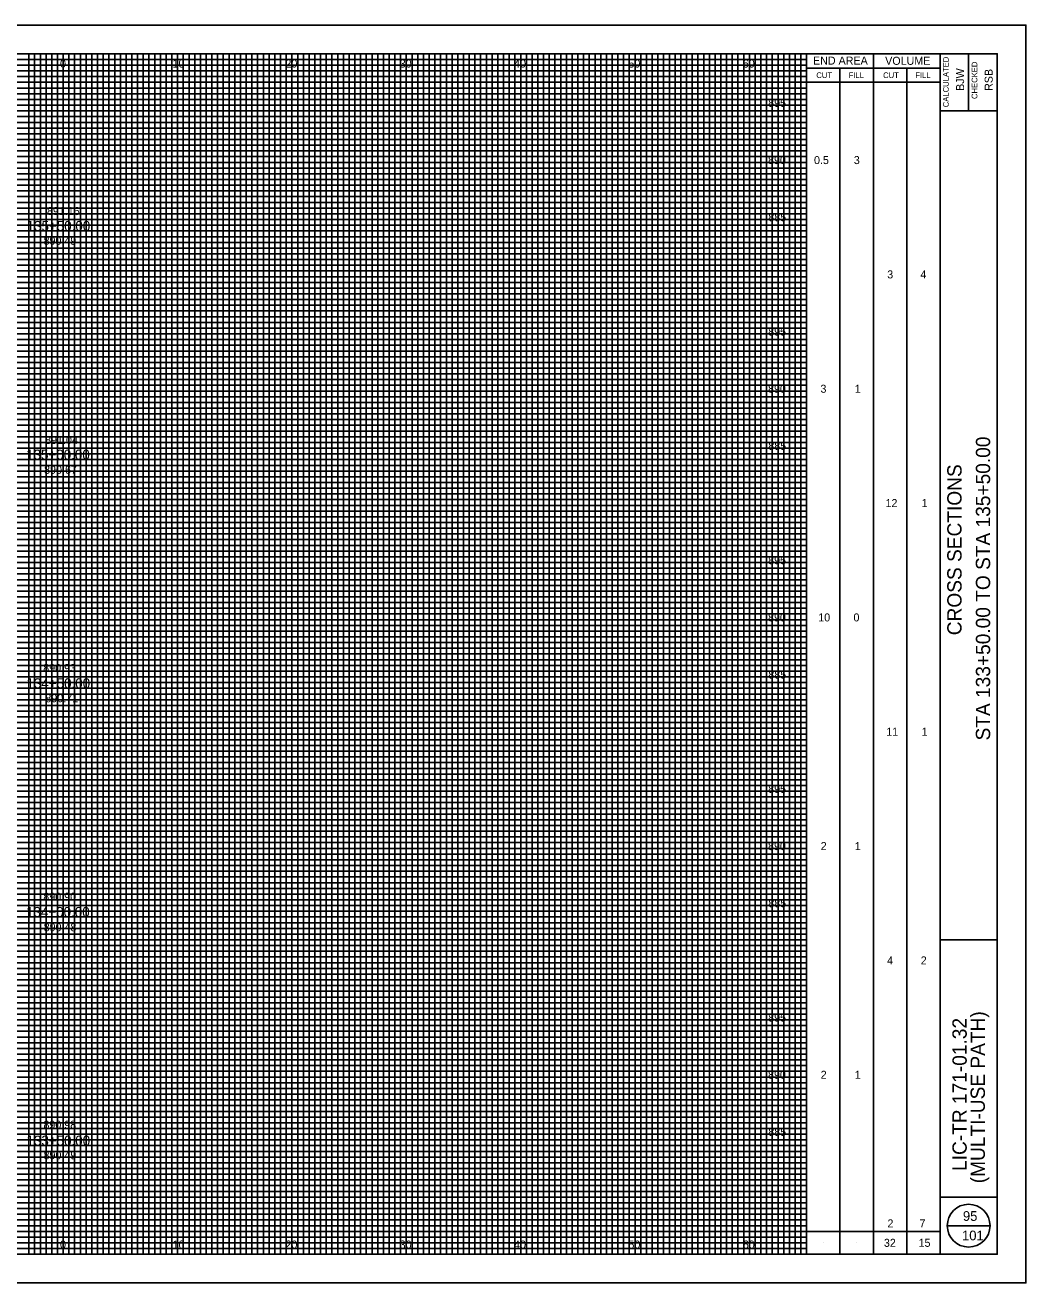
# Model space of a CAD drawing. Extents: x -10 to 160, y -2 to 3672.
# Drawn here: x 72.5 to 160, y 2987.5 to 3097.5 of the extents above; entities that cross this region are included whole.
import ezdxf

# ---------------------------------------------------------------- set-up
doc = ezdxf.new("R2010")
doc.units = 0
for name, color, linetype in [('SH_Border', 7, 'Continuous'), ('SH_Cut_Line', 7, 'Continuous'), ('SH_Data', 7, 'Continuous'), ('SH_Major_Grid_Line', 7, 'Continuous'), ('SH_Minor_Grid_Line', 7, 'Continuous'), ('SH_Text', 7, 'Continuous'), ('TX_P_10', 7, 'Continuous'), ('TX_X_10', 7, 'Continuous')]:
    doc.layers.add(name, color=color, linetype=linetype)

msp = doc.modelspace()

# ---------------------------------------------------------------- linework, layer by layer
at = {"layer": 'SH_Border'}
for p, q in [((152.5, 2990), (152.5, 3095)), ((155, 3095), (155, 3090)), ((152.5, 3090), (157.5, 3090)), ((152.5, 3017.5), (157.5, 3017.5)), ((152.5, 2995), (157.5, 2995))]:
    msp.add_line(p, q, dxfattribs=at)
msp.add_lwpolyline([(0, 3095), (157.5, 3095), (157.5, 2990), (0, 2990)], close=True, dxfattribs=at)
at = {"layer": 'SH_Cut_Line'}
msp.add_lwpolyline([(-10, 2987.5), (160, 2987.5), (160, 3097.5), (-10, 3097.5)], close=True, dxfattribs=at)
at = {"layer": 'SH_Data'}
for p, q in [((140.83, 2990), (140.83, 3095)), ((146.67, 2990), (146.67, 3095)), ((140.83, 3093.75), (152.5, 3093.75)), ((143.75, 2990), (143.75, 3093.75)), ((149.58, 2990), (149.58, 3093.75)), ((140.83, 3092.5), (152.5, 3092.5)), ((140.83, 2992), (152.5, 2992)), ((153.12, 2992.5), (156.88, 2992.5)), ((142.29, 2991), (142.29, 2991)), ((145.21, 2991), (145.21, 2991)), ((148.12, 2991), (148.12, 2991)), ((151.04, 2991), (151.04, 2991))]:
    msp.add_line(p, q, dxfattribs=at)
msp.add_circle((155, 2992.5), 1.87, dxfattribs=at)
at = {"layer": 'SH_Major_Grid_Line'}
for p, q in [((75.83, 2990), (75.83, 3095)), ((80.83, 2990), (80.83, 3095)), ((85.83, 2990), (85.83, 3095)), ((90.83, 2990), (90.83, 3095)), ((95.83, 2990), (95.83, 3095)), ((100.83, 2990), (100.83, 3095)), ((105.83, 2990), (105.83, 3095)), ((110.83, 2990), (110.83, 3095)), ((115.83, 2990), (115.83, 3095)), ((120.83, 2990), (120.83, 3095)), ((125.83, 2990), (125.83, 3095)), ((130.83, 2990), (130.83, 3095)), ((135.83, 2990), (135.83, 3095)), ((5.83, 3090), (140.83, 3090)), ((5.83, 3085), (140.83, 3085)), ((5.83, 3080), (140.83, 3080)), ((5.83, 3075), (140.83, 3075)), ((5.83, 3070), (140.83, 3070)), ((5.83, 3065), (140.83, 3065)), ((5.83, 3060), (140.83, 3060)), ((5.83, 3055), (140.83, 3055)), ((5.83, 3050), (140.83, 3050)), ((5.83, 3045), (140.83, 3045)), ((5.83, 3040), (140.83, 3040)), ((5.83, 3035), (140.83, 3035)), ((5.83, 3030), (140.83, 3030)), ((5.83, 3025), (140.83, 3025)), ((5.83, 3020), (140.83, 3020)), ((5.83, 3015), (140.83, 3015)), ((5.83, 3010), (140.83, 3010)), ((5.83, 3005), (140.83, 3005)), ((5.83, 3000), (140.83, 3000)), ((5.83, 2995), (140.83, 2995))]:
    msp.add_line(p, q, dxfattribs=at)
at = {"layer": 'SH_Minor_Grid_Line'}
for p, q in [((5.83, 3094.5), (140.83, 3094.5)), ((72.83, 2990), (72.83, 3095)), ((73.33, 2990), (73.33, 3095)), ((73.83, 2990), (73.83, 3095)), ((74.33, 2990), (74.33, 3095)), ((74.83, 2990), (74.83, 3095)), ((75.33, 2990), (75.33, 3095)), ((76.33, 2990), (76.33, 3095)), ((76.83, 2990), (76.83, 3095)), ((77.33, 2990), (77.33, 3095)), ((77.83, 2990), (77.83, 3095)), ((78.33, 2990), (78.33, 3095)), ((78.83, 2990), (78.83, 3095)), ((79.33, 2990), (79.33, 3095)), ((79.83, 2990), (79.83, 3095)), ((80.33, 2990), (80.33, 3095)), ((81.33, 2990), (81.33, 3095)), ((81.83, 2990), (81.83, 3095)), ((82.33, 2990), (82.33, 3095)), ((82.83, 2990), (82.83, 3095)), ((83.33, 2990), (83.33, 3095)), ((83.83, 2990), (83.83, 3095)), ((84.33, 2990), (84.33, 3095)), ((84.83, 2990), (84.83, 3095)), ((85.33, 2990), (85.33, 3095)), ((86.33, 2990), (86.33, 3095)), ((86.83, 2990), (86.83, 3095)), ((87.33, 2990), (87.33, 3095)), ((87.83, 2990), (87.83, 3095)), ((88.33, 2990), (88.33, 3095)), ((88.83, 2990), (88.83, 3095)), ((89.33, 2990), (89.33, 3095)), ((89.83, 2990), (89.83, 3095)), ((90.33, 2990), (90.33, 3095)), ((91.33, 2990), (91.33, 3095)), ((91.83, 2990), (91.83, 3095)), ((92.33, 2990), (92.33, 3095)), ((92.83, 2990), (92.83, 3095)), ((93.33, 2990), (93.33, 3095)), ((93.83, 2990), (93.83, 3095)), ((94.33, 2990), (94.33, 3095)), ((94.83, 2990), (94.83, 3095)), ((95.33, 2990), (95.33, 3095)), ((96.33, 2990), (96.33, 3095)), ((96.83, 2990), (96.83, 3095)), ((97.33, 2990), (97.33, 3095)), ((97.83, 2990), (97.83, 3095)), ((98.33, 2990), (98.33, 3095)), ((98.83, 2990), (98.83, 3095)), ((99.33, 2990), (99.33, 3095)), ((99.83, 2990), (99.83, 3095)), ((100.33, 2990), (100.33, 3095)), ((101.33, 2990), (101.33, 3095)), ((101.83, 2990), (101.83, 3095)), ((102.33, 2990), (102.33, 3095)), ((102.83, 2990), (102.83, 3095)), ((103.33, 2990), (103.33, 3095)), ((103.83, 2990), (103.83, 3095)), ((104.33, 2990), (104.33, 3095)), ((104.83, 2990), (104.83, 3095)), ((105.33, 2990), (105.33, 3095)), ((106.33, 2990), (106.33, 3095)), ((106.83, 2990), (106.83, 3095)), ((107.33, 2990), (107.33, 3095)), ((107.83, 2990), (107.83, 3095)), ((108.33, 2990), (108.33, 3095)), ((108.83, 2990), (108.83, 3095)), ((109.33, 2990), (109.33, 3095)), ((109.83, 2990), (109.83, 3095)), ((110.33, 2990), (110.33, 3095)), ((111.33, 2990), (111.33, 3095)), ((111.83, 2990), (111.83, 3095)), ((112.33, 2990), (112.33, 3095)), ((112.83, 2990), (112.83, 3095)), ((113.33, 2990), (113.33, 3095)), ((113.83, 2990), (113.83, 3095)), ((114.33, 2990), (114.33, 3095)), ((114.83, 2990), (114.83, 3095)), ((115.33, 2990), (115.33, 3095)), ((116.33, 2990), (116.33, 3095)), ((116.83, 2990), (116.83, 3095)), ((117.33, 2990), (117.33, 3095)), ((117.83, 2990), (117.83, 3095)), ((118.33, 2990), (118.33, 3095)), ((118.83, 2990), (118.83, 3095)), ((119.33, 2990), (119.33, 3095)), ((119.83, 2990), (119.83, 3095)), ((120.33, 2990), (120.33, 3095)), ((121.33, 2990), (121.33, 3095)), ((121.83, 2990), (121.83, 3095)), ((122.33, 2990), (122.33, 3095)), ((122.83, 2990), (122.83, 3095)), ((123.33, 2990), (123.33, 3095)), ((123.83, 2990), (123.83, 3095)), ((124.33, 2990), (124.33, 3095)), ((124.83, 2990), (124.83, 3095)), ((125.33, 2990), (125.33, 3095)), ((126.33, 2990), (126.33, 3095)), ((126.83, 2990), (126.83, 3095)), ((127.33, 2990), (127.33, 3095)), ((127.83, 2990), (127.83, 3095)), ((128.33, 2990), (128.33, 3095)), ((128.83, 2990), (128.83, 3095)), ((129.33, 2990), (129.33, 3095)), ((129.83, 2990), (129.83, 3095)), ((130.33, 2990), (130.33, 3095)), ((131.33, 2990), (131.33, 3095)), ((131.83, 2990), (131.83, 3095)), ((132.33, 2990), (132.33, 3095)), ((132.83, 2990), (132.83, 3095)), ((133.33, 2990), (133.33, 3095)), ((133.83, 2990), (133.83, 3095)), ((134.33, 2990), (134.33, 3095)), ((134.83, 2990), (134.83, 3095)), ((135.33, 2990), (135.33, 3095)), ((136.33, 2990), (136.33, 3095)), ((136.83, 2990), (136.83, 3095)), ((137.33, 2990), (137.33, 3095)), ((137.83, 2990), (137.83, 3095)), ((138.33, 2990), (138.33, 3095)), ((138.83, 2990), (138.83, 3095)), ((139.33, 2990), (139.33, 3095)), ((139.83, 2990), (139.83, 3095)), ((140.33, 2990), (140.33, 3095)), ((5.83, 3094), (140.83, 3094)), ((5.83, 3093.5), (140.83, 3093.5)), ((5.83, 3093), (140.83, 3093)), ((5.83, 3092.5), (140.83, 3092.5)), ((5.83, 3092), (140.83, 3092)), ((5.83, 3091.5), (140.83, 3091.5)), ((5.83, 3091), (140.83, 3091)), ((5.83, 3090.5), (140.83, 3090.5)), ((5.83, 3089.5), (140.83, 3089.5)), ((5.83, 3089), (140.83, 3089)), ((5.83, 3088.5), (140.83, 3088.5)), ((5.83, 3088), (140.83, 3088)), ((5.83, 3087.5), (140.83, 3087.5)), ((5.83, 3087), (140.83, 3087)), ((5.83, 3086.5), (140.83, 3086.5)), ((5.83, 3086), (140.83, 3086)), ((5.83, 3085.5), (140.83, 3085.5)), ((5.83, 3084.5), (140.83, 3084.5)), ((5.83, 3084), (140.83, 3084)), ((5.83, 3083.5), (140.83, 3083.5)), ((5.83, 3083), (140.83, 3083)), ((5.83, 3082.5), (140.83, 3082.5)), ((5.83, 3082), (140.83, 3082)), ((5.83, 3081.5), (140.83, 3081.5)), ((5.83, 3081), (140.83, 3081)), ((5.83, 3080.5), (140.83, 3080.5)), ((5.83, 3079.5), (140.83, 3079.5)), ((5.83, 3079), (140.83, 3079)), ((5.83, 3078.5), (140.83, 3078.5)), ((5.83, 3078), (140.83, 3078)), ((5.83, 3077.5), (140.83, 3077.5)), ((5.83, 3077), (140.83, 3077)), ((5.83, 3076.5), (140.83, 3076.5)), ((5.83, 3076), (140.83, 3076)), ((5.83, 3075.5), (140.83, 3075.5)), ((5.83, 3074.5), (140.83, 3074.5)), ((5.83, 3074), (140.83, 3074)), ((5.83, 3073.5), (140.83, 3073.5)), ((5.83, 3073), (140.83, 3073)), ((5.83, 3072.5), (140.83, 3072.5)), ((5.83, 3072), (140.83, 3072)), ((5.83, 3071.5), (140.83, 3071.5)), ((5.83, 3071), (140.83, 3071)), ((5.83, 3070.5), (140.83, 3070.5)), ((5.83, 3069.5), (140.83, 3069.5)), ((5.83, 3069), (140.83, 3069)), ((5.83, 3068.5), (140.83, 3068.5)), ((5.83, 3068), (140.83, 3068)), ((5.83, 3067.5), (140.83, 3067.5)), ((5.83, 3067), (140.83, 3067)), ((5.83, 3066.5), (140.83, 3066.5)), ((5.83, 3066), (140.83, 3066)), ((5.83, 3065.5), (140.83, 3065.5)), ((5.83, 3064.5), (140.83, 3064.5)), ((5.83, 3064), (140.83, 3064)), ((5.83, 3063.5), (140.83, 3063.5)), ((5.83, 3063), (140.83, 3063)), ((5.83, 3062.5), (140.83, 3062.5)), ((5.83, 3062), (140.83, 3062)), ((5.83, 3061.5), (140.83, 3061.5)), ((5.83, 3061), (140.83, 3061)), ((5.83, 3060.5), (140.83, 3060.5)), ((5.83, 3059.5), (140.83, 3059.5)), ((5.83, 3059), (140.83, 3059)), ((5.83, 3058.5), (140.83, 3058.5)), ((5.83, 3058), (140.83, 3058)), ((5.83, 3057.5), (140.83, 3057.5)), ((5.83, 3057), (140.83, 3057)), ((5.83, 3056.5), (140.83, 3056.5)), ((5.83, 3056), (140.83, 3056)), ((5.83, 3055.5), (140.83, 3055.5)), ((5.83, 3054.5), (140.83, 3054.5)), ((5.83, 3054), (140.83, 3054)), ((5.83, 3053.5), (140.83, 3053.5)), ((5.83, 3053), (140.83, 3053)), ((5.83, 3052.5), (140.83, 3052.5)), ((5.83, 3052), (140.83, 3052)), ((5.83, 3051.5), (140.83, 3051.5)), ((5.83, 3051), (140.83, 3051)), ((5.83, 3050.5), (140.83, 3050.5)), ((5.83, 3049.5), (140.83, 3049.5)), ((5.83, 3049), (140.83, 3049)), ((5.83, 3048.5), (140.83, 3048.5)), ((5.83, 3048), (140.83, 3048)), ((5.83, 3047.5), (140.83, 3047.5)), ((5.83, 3047), (140.83, 3047)), ((5.83, 3046.5), (140.83, 3046.5)), ((5.83, 3046), (140.83, 3046)), ((5.83, 3045.5), (140.83, 3045.5)), ((5.83, 3044.5), (140.83, 3044.5)), ((5.83, 3044), (140.83, 3044)), ((5.83, 3043.5), (140.83, 3043.5)), ((5.83, 3043), (140.83, 3043)), ((5.83, 3042.5), (140.83, 3042.5)), ((5.83, 3042), (140.83, 3042)), ((5.83, 3041.5), (140.83, 3041.5)), ((5.83, 3041), (140.83, 3041)), ((5.83, 3040.5), (140.83, 3040.5)), ((5.83, 3039.5), (140.83, 3039.5)), ((5.83, 3039), (140.83, 3039)), ((5.83, 3038.5), (140.83, 3038.5)), ((5.83, 3038), (140.83, 3038)), ((5.83, 3037.5), (140.83, 3037.5)), ((5.83, 3037), (140.83, 3037)), ((5.83, 3036.5), (140.83, 3036.5)), ((5.83, 3036), (140.83, 3036)), ((5.83, 3035.5), (140.83, 3035.5)), ((5.83, 3034.5), (140.83, 3034.5)), ((5.83, 3034), (140.83, 3034)), ((5.83, 3033.5), (140.83, 3033.5)), ((5.83, 3033), (140.83, 3033)), ((5.83, 3032.5), (140.83, 3032.5)), ((5.83, 3032), (140.83, 3032)), ((5.83, 3031.5), (140.83, 3031.5)), ((5.83, 3031), (140.83, 3031)), ((5.83, 3030.5), (140.83, 3030.5)), ((5.83, 3029.5), (140.83, 3029.5)), ((5.83, 3029), (140.83, 3029)), ((5.83, 3028.5), (140.83, 3028.5)), ((5.83, 3028), (140.83, 3028)), ((5.83, 3027.5), (140.83, 3027.5)), ((5.83, 3027), (140.83, 3027)), ((5.83, 3026.5), (140.83, 3026.5)), ((5.83, 3026), (140.83, 3026)), ((5.83, 3025.5), (140.83, 3025.5)), ((5.83, 3024.5), (140.83, 3024.5)), ((5.83, 3024), (140.83, 3024)), ((5.83, 3023.5), (140.83, 3023.5)), ((5.83, 3023), (140.83, 3023)), ((5.83, 3022.5), (140.83, 3022.5)), ((5.83, 3022), (140.83, 3022)), ((5.83, 3021.5), (140.83, 3021.5)), ((5.83, 3021), (140.83, 3021)), ((5.83, 3020.5), (140.83, 3020.5)), ((5.83, 3019.5), (140.83, 3019.5)), ((5.83, 3019), (140.83, 3019)), ((5.83, 3018.5), (140.83, 3018.5)), ((5.83, 3018), (140.83, 3018)), ((5.83, 3017.5), (140.83, 3017.5)), ((5.83, 3017), (140.83, 3017)), ((5.83, 3016.5), (140.83, 3016.5)), ((5.83, 3016), (140.83, 3016)), ((5.83, 3015.5), (140.83, 3015.5)), ((5.83, 3014.5), (140.83, 3014.5)), ((5.83, 3014), (140.83, 3014)), ((5.83, 3013.5), (140.83, 3013.5)), ((5.83, 3013), (140.83, 3013)), ((5.83, 3012.5), (140.83, 3012.5)), ((5.83, 3012), (140.83, 3012)), ((5.83, 3011.5), (140.83, 3011.5)), ((5.83, 3011), (140.83, 3011)), ((5.83, 3010.5), (140.83, 3010.5)), ((5.83, 3009.5), (140.83, 3009.5)), ((5.83, 3009), (140.83, 3009)), ((5.83, 3008.5), (140.83, 3008.5)), ((5.83, 3008), (140.83, 3008)), ((5.83, 3007.5), (140.83, 3007.5)), ((5.83, 3007), (140.83, 3007)), ((5.83, 3006.5), (140.83, 3006.5)), ((5.83, 3006), (140.83, 3006)), ((5.83, 3005.5), (140.83, 3005.5)), ((5.83, 3004.5), (140.83, 3004.5)), ((5.83, 3004), (140.83, 3004)), ((5.83, 3003.5), (140.83, 3003.5)), ((5.83, 3003), (140.83, 3003)), ((5.83, 3002.5), (140.83, 3002.5)), ((5.83, 3002), (140.83, 3002)), ((5.83, 3001.5), (140.83, 3001.5)), ((5.83, 3001), (140.83, 3001)), ((5.83, 3000.5), (140.83, 3000.5)), ((5.83, 2999.5), (140.83, 2999.5)), ((5.83, 2999), (140.83, 2999)), ((5.83, 2998.5), (140.83, 2998.5)), ((5.83, 2998), (140.83, 2998)), ((5.83, 2997.5), (140.83, 2997.5)), ((5.83, 2997), (140.83, 2997)), ((5.83, 2996.5), (140.83, 2996.5)), ((5.83, 2996), (140.83, 2996)), ((5.83, 2995.5), (140.83, 2995.5)), ((5.83, 2994.5), (140.83, 2994.5)), ((5.83, 2994), (140.83, 2994)), ((5.83, 2993.5), (140.83, 2993.5)), ((5.83, 2993), (140.83, 2993)), ((5.83, 2992.5), (140.83, 2992.5)), ((5.83, 2992), (140.83, 2992)), ((5.83, 2991.5), (140.83, 2991.5)), ((5.83, 2991), (140.83, 2991)), ((5.83, 2990.5), (140.83, 2990.5))]:
    msp.add_line(p, q, dxfattribs=at)

# ---------------------------------------------------------------- texts
at = {"layer": 'SH_Data'}
for s, height, p in [('END AREA', 0.7, (141.39, 3094.05)), ('VOLUME', 0.7, (147.7, 3094.03)), ('CUT', 0.5, (141.68, 3092.87)), ('FILL', 0.5, (144.5, 3092.87)), ('CUT', 0.5, (147.52, 3092.87)), ('FILL', 0.5, (150.34, 3092.87)), ('95', 0.85, (154.5, 2992.92)), ('101', 0.85, (154.42, 2991.22))]:
    msp.add_text(s, height=height, dxfattribs=at).set_placement(p)
for s, height, p in [('CALCULATED', 0.5, (153.26, 3090.32)), ('BJW', 0.7, (154.6, 3091.75)), ('CHECKED', 0.5, (155.76, 3091.04)), ('RSB', 0.7, (157.1, 3091.75)), ('STA 133+50.00 TO STA 135+50.00', 1.25, (156.88, 3034.94)), ('CROSS SECTIONS', 1.25, (154.38, 3044.14)), ('(MULTI-USE PATH)', 1.25, (156.42, 2996.21)), ('LIC-TR 171-01.32', 1.25, (154.83, 2997.29))]:
    msp.add_text(s, height=height, rotation=90, dxfattribs=at).set_placement(p)
at = {"layer": 'SH_Text'}
for s, height, p in [('0', 0.7, (75.55, 3093.79)), ('10', 0.7, (85.39, 3093.79)), ('20', 0.7, (95.26, 3093.79)), ('30', 0.7, (105.25, 3093.79)), ('40', 0.7, (115.25, 3093.79)), ('50', 0.7, (125.25, 3093.79)), ('60', 0.7, (135.25, 3093.79)), ('895', 0.7, (137.47, 3090.35)), ('890', 0.7, (137.46, 3085.35)), ('0.5', 0.7, (141.48, 3085.35)), ('3', 0.7, (144.96, 3085.35)), ('135+50.00', 0.875, (72.63, 3079.5)), ('885', 0.7, (137.48, 3080.35)), ('3', 0.7, (147.88, 3075.35)), ('4', 0.7, (150.78, 3075.35)), ('895', 0.7, (137.47, 3070.35)), ('890', 0.7, (137.46, 3065.35)), ('3', 0.7, (142.04, 3065.35)), ('1', 0.7, (145.04, 3065.35)), ('135+00.00', 0.875, (72.59, 3059.5)), ('885', 0.7, (137.48, 3060.35)), ('12', 0.7, (147.73, 3055.35)), ('1', 0.7, (150.88, 3055.35)), ('895', 0.7, (137.47, 3050.35)), ('890', 0.7, (137.46, 3045.35)), ('10', 0.7, (141.85, 3045.35)), ('0', 0.7, (144.93, 3045.35)), ('885', 0.7, (137.48, 3040.35)), ('134+50.00', 0.875, (72.62, 3039.5)), ('11', 0.7, (147.79, 3035.35)), ('1', 0.7, (150.88, 3035.35)), ('895', 0.7, (137.47, 3030.35)), ('890', 0.7, (137.46, 3025.35)), ('2', 0.7, (142.06, 3025.35)), ('1', 0.7, (145.04, 3025.35)), ('885', 0.7, (137.48, 3020.35)), ('134+00.00', 0.875, (72.58, 3019.5)), ('4', 0.7, (147.87, 3015.35)), ('2', 0.7, (150.81, 3015.35)), ('895', 0.7, (137.47, 3010.35)), ('890', 0.7, (137.46, 3005.35)), ('2', 0.7, (142.06, 3005.35)), ('1', 0.7, (145.04, 3005.35)), ('885', 0.7, (137.48, 3000.35)), ('133+50.00', 0.875, (72.62, 2999.5)), ('2', 0.7, (147.9, 2992.35)), ('7', 0.7, (150.7, 2992.35)), ('0', 0.7, (75.55, 2990.5)), ('10', 0.7, (85.39, 2990.5)), ('20', 0.7, (95.26, 2990.5)), ('30', 0.7, (105.25, 2990.5)), ('40', 0.7, (115.25, 2990.5)), ('50', 0.7, (125.25, 2990.5)), ('60', 0.7, (135.25, 2990.5)), ('32', 0.7, (147.59, 2990.65)), ('15', 0.7, (150.62, 2990.65))]:
    msp.add_text(s, height=height, dxfattribs=at).set_placement(p)
at = {"layer": 'TX_P_10'}
for s, p in [('891.16', (74.41, 3080.89)), ('891.04', (74.25, 3060.87)), ('890.93', (74.08, 3040.93)), ('890.90', (74.09, 3020.92)), ('890.98', (74.1, 3000.98))]:
    msp.add_text(s, height=0.7, dxfattribs=at).set_placement(p)
at = {"layer": 'TX_X_10'}
for s, p in [('890.49', (74.11, 3078.29)), ('890.67', (74.16, 3058.26)), ('890.71', (74.27, 3038.28)), ('890.48', (74.12, 3018.25)), ('890.49', (74.11, 2998.31))]:
    msp.add_text(s, height=0.7, dxfattribs=at).set_placement(p)

doc.saveas('drawing.dxf')
